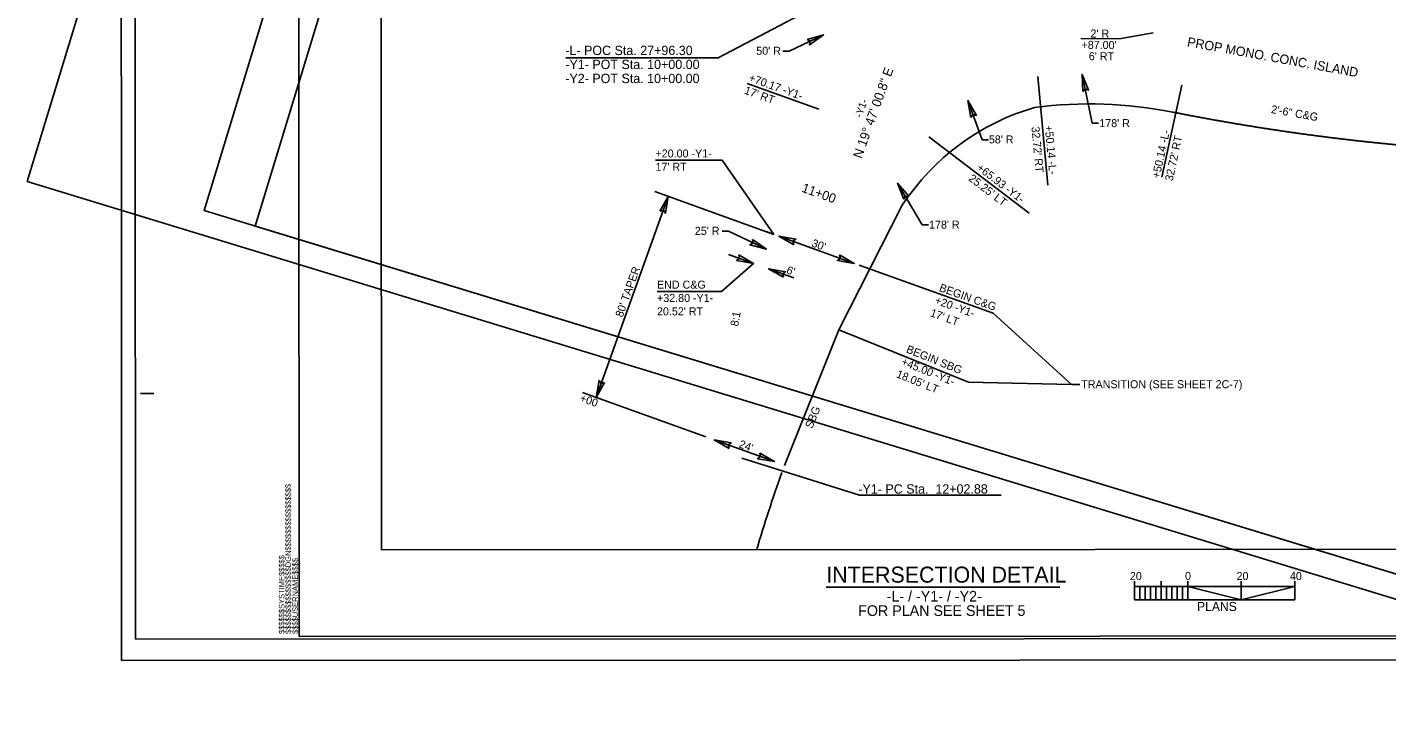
# Model space of a CAD drawing. Extents: x 1443477 to 1619989, y 756574 to 899826.
# Drawn here: x 1619192 to 1619702, y 897805 to 898059 of the extents above; entities that cross this region are included whole.
import ezdxf

# ---------------------------------------------------------------- set-up
doc = ezdxf.new("R2010")
doc.units = 0
for name, color, linetype in [('Default', 7, 'Continuous'), ('Prop Conc 2ft 6in Curb and Gutter', 7, 'Continuous'), ('Prop Dimension', 7, 'Continuous'), ('Prop Guardrail', 7, 'Continuous'), ('Prop Horizontal Alignment Direction Label', 7, 'Continuous'), ('Prop Horizontal Alignment Station Label', 7, 'Continuous'), ('Prop Terminator CELL', 7, 'Continuous'), ('Sheet Clip Boundary CELL', 7, 'Continuous'), ('Sheet Cutting Line CELL', 7, 'Continuous'), ('Sheet Data Field CELL', 7, 'Continuous'), ('Sheet Layout Plan Border', 7, 'Continuous'), ('Sheet Plan CELL', 7, 'Continuous'), ('Sheet Plan Layout CELL', 7, 'Continuous'), ('Sheet Plot Border Inside CELL', 7, 'Continuous'), ('Sheet Plot Border Outside CELL', 7, 'Continuous'), ('Sheet Title CELL', 7, 'Continuous')]:
    doc.layers.add(name, color=color, linetype=linetype)

msp = doc.modelspace()

# ---------------------------------------------------------------- linework, layer by layer
at = {"layer": 'Default'}
msp.add_line((1619491.73, 897849.11), (1619579.24, 897849.14), dxfattribs=at)
msp.add_lwpolyline([(1619324.8, 898243.59), (1619813.94, 898243.79), (1619813.98, 898167.39), (1619859.81, 898167.41), (1619859.94, 897863.4), (1619324.96, 897863.18)], close=True, dxfattribs=at)
at = {"layer": 'Prop Conc 2ft 6in Curb and Gutter'}
for p, q in [((1619614.25, 898056.82), (1619601.54, 898054.54)), ((1619587.21, 898054.63), (1619601.54, 898054.54)), ((1619574.76, 897999.73), (1619571, 898040.49)), ((1619488.99, 898028.18), (1619462.1, 898037.85)), ((1619617.59, 898002.69), (1619625.08, 898037.2)), ((1619567.78, 897989.24), (1619530.18, 898017.88)), ((1619452.74, 898009.13), (1619427.72, 898009.12)), ((1619452.74, 898009.13), (1619472.13, 897981.29)), ((1619464.48, 897970.44), (1619452.51, 897959.88)), ((1619554.27, 897951.75), (1619504.12, 897969.79)), ((1619452.51, 897959.88), (1619428.29, 897959.87)), ((1619545.01, 897926.01), (1619496.51, 897945.53))]:
    msp.add_line(p, q, dxfattribs=at)
at = {"layer": 'Prop Dimension'}
for p, q in [((1619490.74, 898056.02), (1619477.83, 898049.95)), ((1619477.83, 898049.95), (1619475.51, 898049.94)), ((1619587.63, 898041.24), (1619591.46, 898022.99)), ((1619544.83, 898031.44), (1619550.21, 898016.67)), ((1619593.78, 898022.99), (1619591.46, 898022.99)), ((1619552.53, 898016.67), (1619550.21, 898016.67)), ((1619518.49, 898000.48), (1619527.69, 897984.95)), ((1619432.53, 897995.54), (1619405.46, 897920.26)), ((1619472.13, 897981.29), (1619427.45, 897997.37)), ((1619530.01, 897984.95), (1619527.69, 897984.95)), ((1619455.09, 897982.47), (1619452.77, 897982.47)), ((1619469.29, 897975.72), (1619455.09, 897982.47)), ((1619469.25, 897982.33), (1619472.13, 897981.29)), ((1619474.01, 897980.62), (1619502.24, 897970.46)), ((1619464.48, 897970.44), (1619455.07, 897973.83)), ((1619470.13, 897968.41), (1619479.54, 897965.03)), ((1619554.27, 897951.75), (1619583.61, 897925.04)), ((1619545.01, 897926.01), (1619583.61, 897925.04)), ((1619583.61, 897925.04), (1619586.85, 897925.05)), ((1619400.37, 897922.09), (1619446.59, 897905.46)), ((1619449.75, 897904.32), (1619472.34, 897896.2))]:
    msp.add_line(p, q, dxfattribs=at)
at = {"layer": 'Prop Guardrail'}
for p, q in [((1619496.51, 897945.53), (1619520.23, 897992.28)), ((1619476.05, 897894.71), (1619496.51, 897945.53))]:
    msp.add_line(p, q, dxfattribs=at)
for centre, radius, start, end in [((1619590.52, 897870.95), 159.23, 78.786, 97.4583), ((1619594.68, 897943.19), 89.17, 106.1694, 146.5997), ((1619977.61, 897711.39), 534, 160.2164, 163.48)]:
    msp.add_arc(centre, radius, start, end, dxfattribs=at)
for points in [[(1619621.48, 898027.14), (1619622.1, 898027.02), (1619622.41, 898026.96), (1619622.71, 898026.9), (1619623.02, 898026.84), (1619623.33, 898026.78), (1619623.63, 898026.72), (1619623.94, 898026.66), (1619624.25, 898026.6), (1619624.56, 898026.54), (1619624.86, 898026.48), (1619625.17, 898026.42), (1619625.48, 898026.36), (1619625.78, 898026.3), (1619626.09, 898026.24), (1619626.4, 898026.18), (1619626.71, 898026.12), (1619627.01, 898026.06), (1619627.32, 898026), (1619627.63, 898025.94), (1619627.94, 898025.89), (1619628.24, 898025.83), (1619628.55, 898025.77), (1619628.86, 898025.71), (1619629.17, 898025.65), (1619629.47, 898025.59), (1619629.78, 898025.54), (1619630.09, 898025.48), (1619630.4, 898025.42), (1619630.71, 898025.36), (1619631.01, 898025.31), (1619631.32, 898025.25), (1619631.63, 898025.19), (1619631.94, 898025.13), (1619632.24, 898025.08), (1619632.55, 898025.02), (1619632.86, 898024.96), (1619633.17, 898024.91), (1619633.48, 898024.85), (1619633.78, 898024.79), (1619634.09, 898024.74), (1619634.4, 898024.68), (1619634.71, 898024.62), (1619635.01, 898024.57), (1619635.32, 898024.51), (1619635.63, 898024.46), (1619635.94, 898024.4), (1619636.25, 898024.35), (1619636.55, 898024.29), (1619636.86, 898024.24), (1619637.17, 898024.18), (1619637.48, 898024.13), (1619637.79, 898024.07), (1619638.09, 898024.02), (1619638.4, 898023.96), (1619638.71, 898023.91), (1619639.02, 898023.85), (1619639.33, 898023.8), (1619639.64, 898023.74), (1619639.94, 898023.69), (1619640.25, 898023.64), (1619640.56, 898023.58), (1619640.87, 898023.53), (1619641.18, 898023.47), (1619641.49, 898023.42), (1619641.79, 898023.37), (1619642.1, 898023.31), (1619642.41, 898023.26), (1619642.72, 898023.21), (1619643.03, 898023.15), (1619643.34, 898023.1), (1619643.64, 898023.05), (1619643.95, 898023), (1619644.26, 898022.94)], [(1619644.26, 898022.94), (1619645.65, 898022.71), (1619646.34, 898022.59), (1619647.04, 898022.48), (1619647.73, 898022.36), (1619648.42, 898022.25), (1619649.12, 898022.13), (1619649.81, 898022.02), (1619650.51, 898021.91), (1619651.2, 898021.8), (1619651.9, 898021.68), (1619652.59, 898021.57), (1619653.29, 898021.46), (1619653.98, 898021.35), (1619654.68, 898021.24), (1619655.37, 898021.13), (1619656.07, 898021.03), (1619656.76, 898020.92), (1619657.46, 898020.81), (1619658.15, 898020.71), (1619658.85, 898020.6), (1619659.54, 898020.49), (1619660.24, 898020.39), (1619660.93, 898020.29), (1619661.63, 898020.18), (1619662.32, 898020.08), (1619663.02, 898019.98), (1619663.72, 898019.88), (1619664.41, 898019.77), (1619665.11, 898019.67), (1619665.8, 898019.57), (1619666.5, 898019.47), (1619667.2, 898019.38), (1619667.89, 898019.28), (1619668.59, 898019.18), (1619669.29, 898019.08), (1619669.98, 898018.99), (1619670.68, 898018.89), (1619671.38, 898018.8), (1619672.07, 898018.7), (1619672.77, 898018.61), (1619673.47, 898018.51), (1619674.16, 898018.42), (1619674.86, 898018.33), (1619675.56, 898018.24), (1619676.25, 898018.15), (1619676.95, 898018.06), (1619677.65, 898017.97), (1619678.35, 898017.88), (1619679.04, 898017.79), (1619679.74, 898017.7), (1619680.44, 898017.61), (1619681.14, 898017.53), (1619681.83, 898017.44), (1619682.53, 898017.35), (1619683.23, 898017.27), (1619683.93, 898017.18), (1619684.63, 898017.1), (1619685.32, 898017.02), (1619686.02, 898016.93), (1619686.72, 898016.85), (1619687.42, 898016.77), (1619688.12, 898016.69), (1619688.81, 898016.61), (1619689.51, 898016.53), (1619690.21, 898016.45), (1619690.91, 898016.37), (1619691.61, 898016.29), (1619692.31, 898016.22), (1619693, 898016.14), (1619693.7, 898016.06), (1619694.4, 898015.99), (1619695.1, 898015.91), (1619695.8, 898015.84)], [(1619695.8, 898015.84), (1619697.2, 898015.69), (1619697.9, 898015.62), (1619698.59, 898015.55), (1619699.29, 898015.47), (1619699.99, 898015.4), (1619700.69, 898015.33), (1619701.39, 898015.26), (1619702.09, 898015.19), (1619702.79, 898015.12), (1619703.49, 898015.06), (1619704.19, 898014.99), (1619704.89, 898014.92), (1619705.59, 898014.86), (1619706.29, 898014.79), (1619706.99, 898014.73), (1619707.69, 898014.66), (1619708.39, 898014.6), (1619709.09, 898014.53), (1619709.79, 898014.47), (1619710.48, 898014.41), (1619711.18, 898014.35), (1619711.88, 898014.29), (1619712.58, 898014.23), (1619713.28, 898014.17), (1619713.98, 898014.11), (1619714.68, 898014.05), (1619715.38, 898013.99), (1619716.08, 898013.93), (1619716.78, 898013.88), (1619717.48, 898013.82), (1619718.18, 898013.77), (1619718.89, 898013.71), (1619719.59, 898013.66), (1619720.29, 898013.6), (1619720.99, 898013.55), (1619721.69, 898013.5), (1619722.39, 898013.45), (1619723.09, 898013.39), (1619723.79, 898013.34), (1619724.49, 898013.29), (1619725.19, 898013.24), (1619725.89, 898013.19), (1619726.59, 898013.15), (1619727.29, 898013.1), (1619727.99, 898013.05), (1619728.69, 898013), (1619729.39, 898012.96), (1619730.09, 898012.91), (1619730.79, 898012.87), (1619731.49, 898012.82), (1619732.2, 898012.78), (1619732.9, 898012.74), (1619733.6, 898012.69), (1619734.3, 898012.65), (1619735, 898012.61), (1619735.7, 898012.57), (1619736.4, 898012.53), (1619737.1, 898012.49), (1619737.8, 898012.45), (1619738.5, 898012.41), (1619739.2, 898012.38), (1619739.91, 898012.34), (1619740.61, 898012.3), (1619741.31, 898012.27), (1619742.01, 898012.23), (1619742.71, 898012.2), (1619743.41, 898012.16), (1619744.11, 898012.13), (1619744.81, 898012.1), (1619745.51, 898012.06), (1619746.22, 898012.03), (1619746.92, 898012), (1619747.62, 898011.97)]]:
    msp.add_spline(points, degree=3, dxfattribs=at)
at = {"layer": 'Prop Horizontal Alignment Station Label'}
for p, q in [((1619451.2, 898047.41), (1619528.74, 898088.46)), ((1619394.12, 898047.41), (1619451.2, 898047.41)), ((1619504.24, 897883.57), (1619460.07, 897897.55)), ((1619557.25, 897883.59), (1619504.24, 897883.57))]:
    msp.add_line(p, q, dxfattribs=at)
at = {"layer": 'Prop Terminator CELL'}
for points in [[(1619484.57, 898054.32), (1619490.74, 898056.02), (1619485.48, 898052.31), (1619485.73, 898053.67)], [(1619587.86, 898034.85), (1619587.63, 898041.24), (1619590.03, 898035.27), (1619588.77, 898035.83)], [(1619545.97, 898025.15), (1619544.83, 898031.44), (1619548.05, 898025.87), (1619546.72, 898026.24)], [(1619520.76, 897994.51), (1619518.49, 898000.48), (1619522.68, 897995.61), (1619521.31, 897995.73)], [(1619429.38, 897989.98), (1619432.53, 897995.54), (1619431.44, 897989.2), (1619430.66, 897990.33)], [(1619464.07, 897979.41), (1619469.29, 897975.72), (1619463.09, 897977.43), (1619464.3, 897978.1)], [(1619479.57, 897977.46), (1619474.01, 897980.62), (1619480.35, 897979.53), (1619479.21, 897978.75)], [(1619458.92, 897973.6), (1619464.48, 897970.44), (1619458.14, 897971.54), (1619459.27, 897972.32)], [(1619496.68, 897973.62), (1619502.24, 897970.46), (1619495.9, 897971.55), (1619497.03, 897972.34)], [(1619475.69, 897965.26), (1619470.13, 897968.41), (1619476.47, 897967.32), (1619475.33, 897966.54)], [(1619408.61, 897925.82), (1619405.46, 897920.26), (1619406.55, 897926.6), (1619407.33, 897925.46)], [(1619455.31, 897901.17), (1619449.75, 897904.32), (1619456.09, 897903.23), (1619454.96, 897902.45)], [(1619466.78, 897899.35), (1619472.34, 897896.2), (1619466, 897897.29), (1619467.13, 897898.07)]]:
    msp.add_lwpolyline(points, close=True, dxfattribs=at)
at = {"layer": 'Sheet Clip Boundary CELL'}
msp.add_lwpolyline([(1619277.64, 897984.43), (1619813.32, 897821.17), (1619911.11, 898142), (1619838.69, 898164.07), (1619863.35, 898244.99), (1619400.09, 898386.19)], close=True, dxfattribs=at)
at = {"layer": 'Sheet Cutting Line CELL'}
for p, q in [((1619319.88, 898420.04), (1619192.19, 898001.07)), ((1619192.19, 898001.07), (1619836.33, 897804.74))]:
    msp.add_line(p, q, dxfattribs=at)
at = {"layer": 'Sheet Data Field CELL'}
msp.add_line((1619647.33, 897849.45), (1619647.33, 897851.45), dxfattribs=at)
at = {"layer": 'Sheet Layout Plan Border'}
msp.add_lwpolyline([(1619277.64, 897984.43), (1619813.32, 897821.17), (1619911.11, 898142), (1619838.69, 898164.07), (1619863.35, 898244.99), (1619400.09, 898386.19)], close=True, dxfattribs=at)
at = {"layer": 'Sheet Plan CELL'}
for p, q in [((1619234.7, 897921.68), (1619239.7, 897921.68)), ((1619294.13, 897830.71), (1619294.13, 897830.71))]:
    msp.add_line(p, q, dxfattribs=at)
for points in [[(1619294.13, 897830.71), (1619293.94, 898250.7), (1619813.94, 898250.93), (1619813.97, 898190.91), (1619893.98, 898190.94), (1619894.13, 897830.96)], [(1619893.97, 898250.96), (1619293.95, 898250.71), (1619294.13, 897830.71), (1619894.13, 897830.96)]]:
    msp.add_lwpolyline(points, close=True, dxfattribs=at)
at = {"layer": 'Sheet Plan Layout CELL'}
msp.add_lwpolyline([(1619380.95, 898392.01), (1619258.51, 897990.27), (1619832.45, 897815.34), (1619930.23, 898136.17), (1619838.69, 898164.07), (1619863.35, 898244.99)], close=True, dxfattribs=at)
at = {"layer": 'Sheet Plot Border Inside CELL'}
msp.add_lwpolyline([(1619232.74, 897829.68), (1619899.13, 897829.97), (1619898.96, 898251.96), (1619232.56, 898251.68)], close=True, dxfattribs=at)
at = {"layer": 'Sheet Plot Border Outside CELL'}
msp.add_lwpolyline([(1619227.54, 897821.68), (1619900.94, 897821.96), (1619900.76, 898259.96), (1619227.36, 898259.68)], close=True, dxfattribs=at)
at = {"layer": 'Sheet Title CELL'}
for p, q in [((1619607.33, 897849.43), (1619607.33, 897851.43)), ((1619617.33, 897849.43), (1619617.33, 897851.43)), ((1619627.33, 897849.43), (1619627.33, 897851.43)), ((1619647.33, 897849.45), (1619647.33, 897851.44)), ((1619667.33, 897849.46), (1619667.33, 897851.46)), ((1619667.33, 897849.46), (1619607.33, 897849.43)), ((1619647.33, 897849.45), (1619647.33, 897844.45)), ((1619607.33, 897844.43), (1619667.33, 897844.45))]:
    msp.add_line(p, q, dxfattribs=at)
for points in [[(1619607.33, 897849.43), (1619609.33, 897849.43), (1619609.33, 897844.43), (1619607.33, 897844.43)], [(1619611.33, 897849.43), (1619613.33, 897849.43), (1619613.33, 897844.43), (1619611.34, 897844.43)], [(1619615.33, 897849.43), (1619617.33, 897849.43), (1619617.33, 897844.43), (1619615.33, 897844.43)], [(1619619.33, 897849.43), (1619621.33, 897849.44), (1619621.33, 897844.44), (1619619.33, 897844.44)], [(1619623.33, 897849.44), (1619625.33, 897849.44), (1619625.33, 897844.43), (1619623.33, 897844.44)], [(1619627.33, 897849.43), (1619647.33, 897844.45), (1619627.33, 897844.43)], [(1619667.33, 897849.46), (1619647.33, 897844.45), (1619667.33, 897844.45)]]:
    msp.add_lwpolyline(points, close=True, dxfattribs=at)

# ---------------------------------------------------------------- texts
at = {"layer": 'Default'}
for s, height, p in [('INTERSECTION DETAIL', 6, (1619491.74, 897850.85)), ('-L- / -Y1- / -Y2-', 4, (1619514.38, 897843.76)), ('FOR PLAN SEE SHEET 5', 4, (1619503.69, 897838.39))]:
    msp.add_text(s, height=height, rotation=0.0239, dxfattribs=at).set_placement(p)
at = {"layer": 'Prop Conc 2ft 6in Curb and Gutter'}
for s, rotation, p in [("2' R", 359.6395, (1619590.77, 898055.06)), ("+87.00'", 359.6395, (1619587.42, 898050.81)), ("6' RT", 359.6395, (1619590.14, 898046.57)), ('+70.17 -Y1-', 340.2164, (1619462.44, 898038.79)), ("17' RT", 340.2164, (1619460.75, 898034.09)), ("32.72' RT", 275.2664, (1619568.65, 898021.54)), ('+50.14 -L-', 275.2664, (1619573.63, 898022)), ('+50.14 -L-', 77.7594, (1619616.68, 898002.14)), ("32.72' RT", 77.7594, (1619621.57, 898001.08)), ('+20.00 -Y1-', 0.0239, (1619427.72, 898010.12)), ("17' RT", 0.0239, (1619427.72, 898005.12)), ('+65.93 -Y1-', 322.7094, (1619547.86, 898005.7)), ("25.25' LT", 322.7094, (1619544.83, 898001.72)), ('END C&G', 0.0239, (1619428.29, 897960.99)), ('+32.80 -Y1-', 0.0239, (1619428.29, 897955.99)), ('BEGIN C&G', 340.2164, (1619533.83, 897960.16)), ("20.52' RT", 0.0239, (1619428.29, 897950.99)), ("17' LT", 340.2164, (1619530.44, 897950.75)), ('+20 -Y1-', 340.2164, (1619532.14, 897955.46)), ('BEGIN SBG', 338.071, (1619521.46, 897937.17)), ('+45.00 -Y1-', 338.071, (1619519.59, 897932.53)), ("18.05' LT", 338.071, (1619517.72, 897927.89))]:
    msp.add_text(s, height=3, rotation=rotation, dxfattribs=at).set_placement(p)
at = {"layer": 'Prop Dimension'}
for s, height, rotation, p in [('PROP MONO. CONC. ISLAND', 3.5, 349.7101, (1619626.83, 898051.79)), ("50' R", 3, 0.0239, (1619465.5, 898048.59)), ('2\'-6" C&G', 3, 349.9517, (1619658.3, 898026.82)), ("178' R", 3, 0.0239, (1619594.1, 898021.49)), ("58' R", 3, 0.0239, (1619552.69, 898015.38)), ("25' R", 3, 0.0239, (1619442.47, 897981.14)), ("178' R", 3, 0.0239, (1619530.28, 897983.46)), ("30'", 3, 340.2164, (1619485.98, 897976.87)), ("80' TAPER", 3, 70.2164, (1619415.37, 897950.03)), ("6'", 3, 340.2164, (1619476.54, 897966.76)), ('8:1', 3, 79.4463, (1619458.67, 897946.68)), ('TRANSITION (SEE SHEET 2C-7)', 3, 0.0239, (1619587.32, 897923.68)), ('+00', 3, 340.2164, (1619399.1, 897918.86)), ('SBG', 3, 68.1034, (1619486.46, 897908.34)), ("24'", 3, 340.2164, (1619458.75, 897901.59))]:
    msp.add_text(s, height=height, rotation=rotation, dxfattribs=at).set_placement(p)
at = {"layer": 'Prop Horizontal Alignment Direction Label'}
for s, height, p in [('N 19%%d 47\' 00.8" E', 3.5, (1619504.93, 898009.5)), ('-Y1-', 2.8, (1619504.92, 898024.75))]:
    msp.add_text(s, height=height, rotation=70.2164, dxfattribs=at).set_placement(p)
at = {"layer": 'Prop Horizontal Alignment Station Label'}
for s, rotation, p in [('-L- POC Sta. 27+96.30', 360, (1619393.9, 898048.48)), ('-Y1- POT Sta. 10+00.00', 360, (1619393.9, 898043.23)), ('-Y2- POT Sta. 10+00.00 ', 360, (1619393.9, 898037.98)), ('11+00', 340.2164, (1619482.25, 897997.35)), ('-Y1- PC Sta.  12+02.88', 0.0239, (1619503.77, 897884.2))]:
    msp.add_text(s, height=3.5, rotation=rotation, dxfattribs=at).set_placement(p)
at = {"layer": 'Sheet Data Field CELL'}
for s, p in [('20', (1619605.55, 897851.83)), ('20', (1619645.55, 897851.85)), ('40', (1619665.55, 897851.86))]:
    msp.add_text(s, height=3, rotation=0.0239, dxfattribs=at).set_placement(p)
at = {"layer": 'Sheet Plan CELL'}
for s, p in [('$$$$$$$$$$$$$$$$DGN$$$$$$$$$$$$$$$$', (1619291.07, 897831.66)), ('$$$$$$SYSTIME$$$$$', (1619288.64, 897831.64)), ('$$$$USERNAME$$$$', (1619293.69, 897831.66))]:
    msp.add_text(s, height=2.1, rotation=90.0239, dxfattribs=at).set_placement(p)
at = {"layer": 'Sheet Title CELL'}
for s, height, p in [('0', 3, (1619626.23, 897851.89)), ('PLANS', 3.4, (1619630.73, 897840.24))]:
    msp.add_text(s, height=height, rotation=0.0239, dxfattribs=at).set_placement(p)

doc.saveas('drawing.dxf')
